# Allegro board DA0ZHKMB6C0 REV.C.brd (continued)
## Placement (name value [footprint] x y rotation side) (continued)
Q32  pj4n3kdw  [SC70-2_1-65-6P]  93.01 54.23 180 bottom
Q33  2n7002k  [SOT23_213-3_3-2]  138.5 47.32 270 bottom
Q34  2n7002k  [SOT23_213-3_3-2]  137 40.79 180 bottom
Q35  dtc144eua  [UMT_213-3-1_3]  132.81 40.67 0 bottom
Q36  2n7002k  [SOT23_213-3_3-2]  131.92 37.36 270 bottom
Q39  mmbt3904  [UMT_213-3-1_3]  25.37 9.17 180 bottom
Q40  pj4n3kdw  [SC70-2_1-65-6P]  48.23 74.7 180 top
Q41  2n7002k  [SOT23_213-3_3-2]  127.7 42.29 90 bottom
Q42  2n7002  [SOT23_213-3_3-2]  58.97 22.63 0 bottom
Q45  2n7002  [SOT23_213-3_3-2]  62.7 22.53 90 bottom
Q46  pj4n3kdw  [SC70-2_1-65-6P]  22.17 47.32 180 top
Q50  pj4n3kdw  [SC70-2_1-65-6P]  25.7 30.51 270 bottom
Q51  pj4n3kdw  [SC70-2_1-65-6P]  23.33 30.51 90 bottom
Q53  pj4n3kdw  [SC70-2_1-65-6P]  93.18 57.68 180 bottom
R7  *100/f_4  [RC0402]  64.66 87.35 0 top
R8  *100/f_4  [RC0402]  66.77 87.38 0 top
R9  *100/f_4  [RC0402]  69.05 87.38 0 top
R10  *100/f_4  [RC0402]  71.37 87.35 0 top
R11  2.2k_4  [RC0402]  62.2 87.11 0 top
R12  10_4  [RC0402]  85.56 85.62 90 top
R13  10_4  [RC0402]  86.58 85.62 90 top
R14  2.2k_4  [RC0402]  58 86.39 180 top
R15  *10k_4  [RC0402]  90.11 22.17 270 bottom
R17  *0/short_4  [SHORT0402]  88.74 84.35 270 top
R18  *0/short_4  [SHORT0402]  89.75 84.35 270 top
R19  10_4  [RC0402]  91.41 84.35 90 top
R20  10_4  [RC0402]  92.42 84.35 90 top
R21  *0/short_4  [SHORT0402]  22.09 83.77 180 bottom
R22  39.2k/f_4  [RC0402]  10.86 75.26 0 top
R23  *0/short_4  [SHORT0402]  13.63 64.39 135 top
R24  10k/f_4  [RC0402]  61.69 83.21 180 top
R25  *0/short_4  [SHORT0402]  15.05 66.07 180 top
R26  *0/short_4  [SHORT0402]  11.47 62.94 90 top
R27  56/f_4  [RC0402]  14.67 78.26 0 top
R28  *10k_4  [RC0402]  89.53 20.6 180 bottom
R29  *0/short_4  [SHORT0402]  159.56 81.56 180 top
R30  2.2k_4  [RC0402]  25.75 80.98 180 top
R31  200k/f_4  [RC0402]  44.14 75.13 270 top
R32  *0/short_4  [SHORT0402]  159.56 80.54 180 top
R33  0/j_8  [RC0805]  12.01 72.97 270 top
R34  *0/short_4  [SHORT0402]  78.6 82.88 0 top
R35  100k/j_4  [RC0402]  25.75 79.88 180 top
R36  *0/short_4  [SHORT0402]  91.61 76.2 90 top
R37  0/j_8  [RC0805]  28.52 80.47 180 top
R40  *0/short_4  [SHORT0402]  159.56 79.53 180 top
R41  10k_4  [RC0402]  87.32 76.78 0 top
R42  1m_4  [RC0402]  70.04 76.53 180 top
R44  *10k_4  [RC0402]  84.18 81.17 90 top
R45  20k/f_4  [RC0402]  27.14 78.87 180 top
R46  *0/short_4  [SHORT0402]  159.56 78.51 180 top
R47  *0/short_4  [SHORT0402]  16.22 78.26 90 top
R48  *10k_4  [RC0402]  72.64 79.25 270 top
R49  100k/f_4  [RC0402]  72.69 77.11 270 top
R50  *0/short_4  [SHORT0402]  159.56 77.5 180 top
R51  4.7k_4  [RC0402]  28.77 77.37 90 top
R52  47k_4  [RC0402]  31.31 78.31 270 top
R53  100k/f_4  [RC0402]  14.67 76.66 0 top
R54  10k_4  [RC0402]  85.32 81.17 270 top
R55  45.3/f_4  [RC0402]  75.75 77.12 90 top
R56  *0/short_4  [SHORT0402]  73.7 77.9 90 top
R57  *0_4  [RC0402]  74.72 77.11 90 top
R58  100k/f_4  [RC0402]  85.16 75.54 180 top
R59  10m_4  [RC0402]  79.54 76.66 0 top
R60  *10k_4  [RC0402]  85.16 68.55 180 top
R61  *10k_4  [RC0402]  87.54 67.39 0 top
R62  4.7k_4  [RC0402]  45.69 76.56 0 top
R63  200/f_4  [RC0402]  89.45 76.78 0 top
R64  *10k_4  [RC0402]  85.23 76.78 0 top
R65  33_4  [RC0402]  27.37 75.34 0 top
R66  56/f_4  [RC0402]  14.67 81.36 0 top
R67  4.7k_4  [RC0402]  45.43 74.45 270 top
R68  2.2k_4  [RC0402]  16.35 74.57 180 top
R70  *100k/f_4  [RC0402]  36.36 70.6 90 top
R71  *100k/f_4  [RC0402]  37.63 70.6 90 top
R73  2.2k_4  [RC0402]  51.78 70.64 180 top
R74  10k_4  [RC0402]  53.97 70.84 180 top
R79  2.2k_4  [RC0402]  51.78 69.14 180 top
R80  2.2k_4  [RC0402]  53.94 69.14 180 top
R81  *10k_4  [RC0402]  85.46 67.54 180 top
R82  *1k_4  [RC0402]  26.76 70.13 0 top
R83  *0/short_4  [SHORT0402]  51.78 68.1 0 top
R84  4.7k_4  [RC0402]  53.94 68.1 180 top
R85  ntpm@10k_4  [RC0402]  86.02 67.67 0 bottom
R86  *0_4  [RC0402]  90.77 67.69 180 bottom
R87  *0_4  [RC0402]  95.83 70.59 270 bottom
R88  *10k_4  [RC0402]  85.44 65.84 270 top
R90  22_4  [RC0402]  53.94 67.08 180 top
R91  1/f_4  [RC0402]  137.25 67.08 270 top
R92  1/f_4  [RC0402]  138.27 67.08 270 top
R93  1/f_4  [RC0402]  139.41 67.08 270 top
R94  1/f_4  [RC0402]  140.55 67.08 270 top
R95  1/f_4  [RC0402]  141.7 67.08 270 top
R96  1/f_4  [RC0402]  142.84 67.08 270 top
R97  2.49k/f_4  [RC0402]  143.98 67.46 90 top
R98  22_4  [RC0402]  51.78 66.85 180 top
R99  1/f_4  [RC0402]  135.09 66.83 270 top
R100  1/f_4  [RC0402]  136.24 66.83 270 top
R101  10k_4  [RC0402]  30.8 70.74 0 top
R102  33_4  [RC0402]  51.81 65.84 0 top
R103  33_4  [RC0402]  53.94 65.71 0 top
R104  10k_4  [RC0402]  86.96 65.89 0 top
R105  10k_4  [RC0402]  89.65 65.25 0 top
R106  *0/short_6  [SHORT0603]  25.49 64.67 270 top
R107  *0/short_6  [SHORT0603]  26.76 64.67 270 top
R108  22_4  [RC0402]  51.76 63.58 0 top
R109  33_4  [RC0402]  51.76 64.62 0 top
R110  33_4  [RC0402]  53.94 64.67 0 top
R111  *100k/j_4  [RC0402]  24.35 64.67 90 top
R112  *10k_4  [RC0402]  103.22 64.67 270 top
R113  10k_4  [RC0402]  104.23 65.35 270 top
R114  100k/f_4  [RC0402]  105.25 64.67 270 top
R115  10k_4  [RC0402]  107.53 64.16 180 top
R116  *0/short_4  [SHORT0402]  85.31 64.03 180 top
R117  22_4  [RC0402]  53.94 63.63 0 top
R118  560_4  [RC0402]  49.62 64.67 180 top
R119  560_4  [RC0402]  49.67 63.65 180 top
R120  *0/short_4  [SHORT0402]  90.03 62.97 180 top
R121  *0/short_4  [SHORT0402]  85.31 63.02 180 top
R122  *0/short_4  [SHORT0402]  32.71 62.99 0 top
R124  10k_4  [RC0402]  31.31 76.28 270 top
R127  73.2/f_4  [RC0402]  89.85 60.68 0 top
R128  71.5/f_4  [RC0402]  89.63 61.87 180 top
R129  20/f_4  [RC0402]  85.31 61.75 180 top
R130  *0/short_4  [SHORT0402]  91.79 61.75 180 top
R131  *0/short_4  [SHORT0402]  97.37 61.24 0 top
R133  10k_4  [RC0402]  107.74 61.27 180 top
R134  *0/short_4  [SHORT0402]  85.18 60.73 0 top
R135  16.9r_4  [RC0402]  87.6 60.73 180 top
R139  *0/short_4  [SHORT0402]  97.37 60.1 0 top
R140  *2.2k_4  [RC0402]  53.48 60.2 270 top
R144  10k_4  [RC0402]  107.88 59.42 180 top
R145  *2.2k_4  [RC0402]  52.92 58.6 0 top
R146  10k_4  [RC0402]  87.6 58.57 180 top
R147  *10k_4  [RC0402]  89.88 58.57 0 top
R148  *0/short_6  [SHORT0603]  45.63 58.01 90 top
R149  *0/short_6  [SHORT0603]  44.01 58.01 90 top
R150  10k_4  [RC0402]  145.63 57.94 270 top
R153  *4.7k_4  [RC0402]  47.84 57.3 0 top
R154  620/f_4  [RC0402]  97.68 56.03 0 top
R155  *2.2k_4  [RC0402]  52.9 57.48 0 top
R156  *2.2k_4  [RC0402]  52.85 56.21 0 top
R159  *0/short_4  [SHORT0402]  99.28 55.02 180 top
R160  10k/j_4  [RC0402]  118.58 54.76 0 top
R161  *0_4  [RC0402]  99.28 54 0 top
R162  10k/j_4  [RC0402]  23.46 38.61 0 bottom
R163  402/f_4  [RC0402]  63.97 65.94 180 bottom
R164  10k/j_4  [RC0402]  118.58 52.48 0 top
R165  2.2_6  [RC0603]  129.89 51.46 180 top
R166  0/j_6  [RC0603]  124.55 51.08 90 top
R167  8.2k_4  [RC0402]  55.29 64.16 0 bottom
R171  100k/f_4  [RC0402]  132.3 48.54 270 top
R172  *0_4  [RC0402]  40.35 48.29 180 top
R173  *0/short_4  [SHORT0402]  140.05 48.03 180 top
R178  tpm@2.2_6  [RC0603]  49.97 37.8 180 top
R180  *20k_4  [RC0402]  43.12 37.59 270 top
R181  tpm_i@4.7k_4  [RC0402]  45.15 37.59 90 top
R182  *4.7k_4  [RC0402]  44.14 37.59 90 top
R184  100k_4  [RC0402]  22.77 44.86 270 top
R185  100k_4  [RC0402]  23.79 44.86 270 top
R186  10k_4  [RC0402]  19.89 56.01 0 top
R187  1m_4  [RC0402]  26.74 33.12 0 bottom
R188  *0/short_6  [SHORT0603]  10 9.8 270 top
R189  *0/short_6  [SHORT0603]  11.65 9.8 270 top
R190  *0/short_6  [SHORT0603]  13.3 9.8 270 top
R191  *0/short_6  [SHORT0603]  14.82 9.55 270 top
R192  100/f_4  [RC0402]  54.58 84.68 0 bottom
R193  100/f_4  [RC0402]  77.79 95.45 180 bottom
R194  560_4  [RC0402]  77.79 98.5 180 bottom
R195  560_4  [RC0402]  56.61 83.54 180 bottom
R196  10k_4  [RC0402]  163.25 99.09 0 bottom
R197  *0/short_4  [SHORT0402]  54.58 82.27 180 bottom
R198  *0_4  [RC0402]  56.61 82.27 180 bottom
R200  0/j_4  [RC0402]  165.91 97.69 180 bottom
R201  *0/j_4  [RC0402]  162.1 96.93 180 bottom
R202  *0/j_4  [RC0402]  165.91 96.67 180 bottom
R203  4.7k_4  [RC0402]  163.63 96.42 270 bottom
R204  *0/j_4  [RC0402]  162.1 95.78 180 bottom
R205  *0/j_4  [RC0402]  165.91 95.66 180 bottom
R206  10k_4  [RC0402]  62.58 89.69 270 bottom
R207  *0/short_8  [SHORT0805]  165.79 89.56 270 bottom
R208  620/f_4  [RC0402]  64.1 89.43 270 bottom
R209  620/f_4  [RC0402]  65.12 89.43 270 bottom
R210  620/f_4  [RC0402]  66.26 89.43 270 bottom
R211  620/f_4  [RC0402]  67.28 89.43 270 bottom
R212  620/f_4  [RC0402]  68.55 89.43 270 bottom
R213  620/f_4  [RC0402]  69.56 89.43 270 bottom
R214  620/f_4  [RC0402]  70.83 89.43 270 bottom
R215  620/f_4  [RC0402]  71.85 89.43 270 bottom
R216  *0/j_4  [RC0402]  162.61 87.78 0 bottom
R217  0/j_4  [RC0402]  162.61 86.77 0 bottom
R218  2.2k_4  [RC0402]  62.32 87.27 90 bottom
R219  2.2k_4  [RC0402]  63.34 87.27 90 bottom
R220  100k/f_4  [RC0402]  59.27 86.26 180 bottom
R221  *100k/f_4  [RC0402]  62.09 83.08 90 bottom
R222  *4.7k_4  [RC0402]  159.18 82.19 90 bottom
R223  *4.7k_4  [RC0402]  160.33 82.19 90 bottom
R224  *1m_8  [RC0805]  144.47 83.69 270 bottom
R225  75/f_8  [RC0805]  130.39 82.6 90 bottom
R226  75/f_8  [RC0805]  133.75 82.6 90 bottom
R227  75/f_8  [RC0805]  137.43 82.6 90 bottom
R228  75/f_8  [RC0805]  140.61 82.07 90 bottom
R230  *10k_4  [RC0402]  83.61 79.02 0 bottom
R231  10k/f_4  [RC0402]  163.37 77.88 270 bottom
R232  4.7k_4  [RC0402]  163.37 75.72 270 bottom
R233  *0_4  [RC0402]  22.42 37.39 270 top
R234  1m_4  [RC0402]  22.8 27.28 90 bottom
R235  10k_4  [RC0402]  95.98 74.65 270 bottom
R236  100/f_4  [RC0402]  59.02 74.57 180 bottom
R237  10k_4  [RC0402]  56.73 74.45 180 bottom
R238  *0/short_4  [SHORT0402]  78.32 73.05 0 bottom
R239  10k_4  [RC0402]  57.5 72.77 90 bottom
R240  *0/short_4  [SHORT0402]  76.24 72.32 90 bottom
R241  10k_4  [RC0402]  96.49 72.29 0 bottom
R242  10k_4  [RC0402]  58.56 72.97 90 bottom
R243  10k_4  [RC0402]  55.06 71.88 270 bottom
R244  *0/short_4  [SHORT0402]  83.2 70.89 0 bottom
R245  *10k_4  [RC0402]  96.79 68.3 90 top
R246  10k_4  [RC0402]  56.48 72.72 90 bottom
R247  45.3/f_4  [RC0402]  80.48 70.38 90 bottom
R248  1k/f_4  [RC0402]  78.14 70.28 270 bottom
R249  1k/f_4  [RC0402]  79.16 70.28 270 bottom
R250  51/f_4  [RC0402]  77.13 70.26 90 bottom
R251  51/f_4  [RC0402]  83.6 69.78 180 bottom
R252  *0/short_4  [SHORT0402]  56.73 69.62 180 bottom
R253  *10k_4  [RC0402]  53.86 69.77 90 bottom
R254  *10k_4  [RC0402]  54.88 69.77 270 bottom
R255  4.02k/f_4  [RC0402]  71.47 69.3 180 bottom
R256  *10k_4  [RC0402]  50.38 73.56 0 bottom
R257  *0/short_4  [SHORT0402]  74.76 68.89 270 bottom
R258  1.24k/f_4  [RC0402]  75.78 68.89 90 bottom
R259  51/f_4  [RC0402]  83.6 68.76 180 bottom
R260  *10k_4  [RC0402]  56.86 70.89 0 bottom
R261  47.5/f_4  [RC0402]  71.47 68.29 180 bottom
R262  51/f_4  [RC0402]  81.42 68.2 270 bottom
R263  402/f_4  [RC0402]  65.68 69.55 0 bottom
R264  402/f_4  [RC0402]  67.53 67.97 270 bottom
R265  *10k_4  [RC0402]  54.32 67.84 180 bottom
R266  10k_4  [RC0402]  94 67.32 180 bottom
R267  51/f_4  [RC0402]  83.53 67.72 180 bottom
R268  *10k_4  [RC0402]  95.65 68.33 90 top
R269  *10k_4  [RC0402]  53.94 66.7 180 bottom
R270  *0_4  [RC0402]  76.67 66.4 0 bottom
R271  tpm@10k_4  [RC0402]  83.53 66.7 0 bottom
R272  *0/short_4  [SHORT0402]  71.16 66.24 0 bottom
R273  *0_4  [RC0402]  60.67 66.19 180 bottom
R274  22_4  [RC0402]  54.32 65.68 180 bottom
R275  *0/short_4  [SHORT0402]  32.38 64.31 180 bottom
R276  100k/f_4  [RC0402]  34.41 64.31 0 bottom
R277  *0/short_4  [SHORT0402]  36.44 64.31 180 bottom
R278  *0/short_8  [SHORT0805]  148.05 64.8 270 bottom
R279  22_4  [RC0402]  55.29 63.09 180 bottom
R280  10k_4  [RC0402]  88.1 64.31 270 bottom
R281  *0/short_4  [SHORT0402]  101.31 59.51 180 bottom
R282  *0/short_4  [SHORT0402]  85.26 64.37 0 bottom
R283  *0/short_4  [SHORT0402]  98.39 64.29 0 bottom
R284  49.9/f_4  [RC0402]  57.65 63.55 0 bottom
R285  49.9/f_4  [RC0402]  58.64 66.19 180 bottom
R286  49.9/f_4  [RC0402]  62.07 68.43 90 bottom
R287  *0/short_4  [SHORT0402]  86.96 63.4 270 bottom
R288  *0/short_4  [SHORT0402]  85.26 63.35 0 bottom
R289  2.2k_4  [RC0402]  98.39 63.27 180 bottom
R290  *0/short_4  [SHORT0402]  87.98 62.18 90 bottom
R291  10k_4  [RC0402]  85 62.28 0 bottom
R292  *0_4  [RC0402]  54.19 62.08 180 bottom
R293  49.9/f_4  [RC0402]  58.18 61.6 0 bottom
R294  *0/short_4  [SHORT0402]  31.74 61.14 180 bottom
R295  10k_4  [RC0402]  85.05 61.2 0 bottom
R296  100/f_4  [RC0402]  74.39 60.86 180 bottom
R297  *100k_4  [RC0402]  35.02 74.19 90 top
R298  *10k_4  [RC0402]  148.71 60.68 180 bottom
R299  49.9/f_4  [RC0402]  75.66 62.13 180 bottom
R300  200k/f_4  [RC0402]  90.01 60.33 0 bottom
R301  10k_4  [RC0402]  85.06 60.19 0 bottom
R302  0.2a/600ohm_6  [RC0603]  54.58 60.25 90 bottom
R303  2.2k_4  [RC0402]  77.44 57.68 180 bottom
R304  10k_4  [RC0402]  90.01 59.31 180 bottom
R305  3.3k/f_4  [RC0402]  87.64 62.41 270 top
R306  100k/j_4  [RC0402]  105.38 59.08 270 bottom
R307  10k/f_4  [RC0402]  34.26 58.9 270 bottom
R308  *47k_4  [RC0402]  103.85 58.83 180 bottom
R309  *0/short_4  [SHORT0402]  48 58.17 0 bottom
R310  0/j_4  [RC0402]  131.79 58.57 270 bottom
R311  0/j_4  [RC0402]  133.06 58.57 270 bottom
R312  *10k_4  [RC0402]  60.87 58.47 90 bottom
R313  *0/short_6  [SHORT0603]  142.84 58.45 270 bottom
R314  100/f_4  [RC0402]  75.91 60.48 270 bottom
R315  *0/short_4  [SHORT0402]  90.11 58.24 0 bottom
R316  0_4  [RC0402]  12.11 56.9 270 top
R317  10k_4  [RC0402]  54.32 58.06 180 bottom
R318  3.3k/f_4  [RC0402]  134.97 58.95 0 bottom
R319  3.3k/f_4  [RC0402]  137 58.06 180 bottom
R320  *10k_4  [RC0402]  92.4 67.87 90 bottom
R321  *0/short_4  [SHORT0402]  80.86 57.18 90 bottom
R322  *0/j_4  [RC0402]  105.38 57.05 270 bottom
R323  10k_4  [RC0402]  90.52 56.67 90 bottom
R324  *10k_4  [RC0402]  96.84 70.59 90 bottom
R325  *0/short_4  [SHORT0402]  47.95 55.78 0 bottom
R326  *0/short_4  [SHORT0402]  89.53 19.51 180 bottom
R327  *10k_6_ntc  [RC0603]  137.9 55.78 90 bottom
R328  10k_4  [RC0402]  90.01 55.02 0 bottom
R329  *15k_4  [RC0402]  150.46 54.76 90 bottom
R330  1k_4  [RC0402]  152.11 54.76 270 bottom
R331  *0/short_4  [SHORT0402]  47.95 54.74 0 bottom
R332  *0/short_6  [SHORT0603]  59.73 54.31 0 bottom
R333  *0/short_4  [SHORT0402]  57.88 53.87 270 bottom
R334  *0/short_4  [SHORT0402]  62.27 53.77 180 bottom
R335  *0/short_4  [SHORT0402]  47.95 53.62 0 bottom
R336  100k/f_4  [RC0402]  67.6 53.14 180 bottom
R337  *0_4  [RC0402]  137.38 52.73 90 bottom
R338  4.7k_4  [RC0402]  95.67 52.68 90 bottom
R339  100k/f_4  [RC0402]  67.6 52.12 180 bottom
R340  *0/short_8  [SHORT0805]  56.48 51.84 180 bottom
R341  *0/short_8  [SHORT0805]  56.48 49.66 180 bottom
R342  4.7k_4  [RC0402]  67.09 49.43 0 bottom
R343  100k/f_4  [RC0402]  145.76 48.41 180 bottom
R344  4.7k_4  [RC0402]  67.09 48.21 180 bottom
R345  *10k/j_4  [RC0402]  137.63 50.83 0 bottom
R346  *0/short_6  [SHORT0603]  56.23 47.88 180 bottom
R347  29.4/f_4  [RC0402]  68.74 47.68 270 bottom
R348  162/f_4  [RC0402]  69.76 47.68 90 bottom
R349  23.2/f_4  [RC0402]  70.78 47.68 270 bottom
R350  *0/short_4  [SHORT0402]  112.3 14.98 270 bottom
R351  *1.24k/f_4  [RC0402]  74.41 71.07 180 bottom
R352  *0/short_4  [SHORT0402]  132.17 46.25 270 bottom
R353  0/j_4  [RC0402]  134.2 46.25 90 bottom
R354  0/j_4  [RC0402]  135.35 46.25 90 bottom
R355  1m_4  [RC0402]  14.09 37.64 90 bottom
R356  1m_4  [RC0402]  16.15 38.35 0 bottom
R357  0/j_6  [RC0603]  141.57 44.81 0 bottom
R358  100k/j_4  [RC0402]  134.97 43.71 270 bottom
R359  *100k_4  [RC0402]  131.92 44.22 270 bottom
R360  *0/short_6  [SHORT0603]  142.51 88.01 180 bottom
R361  2.2_6  [RC0603]  137.76 43.97 90 bottom
R362  100k/j_4  [RC0402]  145.76 43.97 180 bottom
R363  0_4  [RC0402]  21.54 54.92 0 top
R364  4.7k_4  [RC0402]  95.62 55.58 270 bottom
R365  *0_4  [RC0402]  22.37 53.37 90 top
R366  *47k/f_4  [RC0402]  145.76 42.82 180 bottom
R367  10k_4  [RC0402]  102.2 64.16 270 top
R368  100k/f_4  [RC0402]  145.76 41.81 180 bottom
R370  10k_4  [RC0402]  123.79 41.3 0 bottom
R371  10k_4  [RC0402]  130.57 40.95 270 bottom
R372  *0/short_4  [SHORT0402]  123.79 40.28 0 bottom
R373  *0/short_4  [SHORT0402]  145.76 39.78 0 bottom
R374  *43_4  [RC0402]  123.79 39.27 180 bottom
R375  *0/short_4  [SHORT0402]  145.76 38.76 0 bottom
R376  2.2_6  [RC0603]  141.44 38.51 180 bottom
R377  *100k_4  [RC0402]  134.33 38.25 270 bottom
R378  4.7k_4  [RC0402]  141.61 37.13 0 bottom
R382  10k/j_4  [RC0402]  123.77 38.25 0 bottom
R383  10k/j_4  [RC0402]  146.07 38.61 0 top
R384  4.7k_4  [RC0402]  141.92 36.11 0 bottom
R385  *10k_4  [RC0402]  134.33 36.09 90 bottom
R386  10k/j_4  [RC0402]  147.14 37.07 90 top
R387  *100k/f_4  [RC0402]  123.92 35.13 0 bottom
R388  4.7k/f_4  [RC0402]  103.47 35.08 180 bottom
R389  10k/f_4  [RC0402]  47.02 34.82 180 bottom
R390  *0/short_6  [SHORT0603]  105.19 34.82 270 bottom
R391  4.7k_4  [RC0402]  123.79 34.11 0 bottom
R392  4.7k/f_4  [RC0402]  103.47 34.06 0 bottom
R393  10k/f_4  [RC0402]  47.02 33.8 180 bottom
R394  *10k_4  [RC0402]  147.71 34.83 180 bottom
R395  10k_4  [RC0402]  123.79 33.1 0 bottom
R396  *0_6  [RC0603]  105.63 32.41 0 bottom
R397  4.7k/f_4  [RC0402]  65.12 29.87 0 bottom
R398  *10k/f_4  [RC0402]  46.51 29.61 180 bottom
R399  4.7k/f_4  [RC0402]  63.59 25.81 0 bottom
R401  *0_6  [RC0603]  65.19 22.76 90 bottom
R402  *0/short_8  [SHORT0805]  161.38 23.65 270 bottom
R404  2.2k_4  [RC0402]  49.75 17.63 180 bottom
R405  10k_4  [RC0402]  52.54 19.81 90 bottom
R406  10k_4  [RC0402]  53.56 19.84 90 bottom
R407  *0/short_8  [SHORT0805]  57.09 17.09 0 bottom
R408  2.2k_4  [RC0402]  47.59 17.63 0 bottom
R411  *0_8  [RC0805]  57.09 19.1 0 bottom
R412  1k_4  [RC0402]  29.05 9.04 90 bottom
R413  20k_4  [RC0402]  37.05 10.44 270 bottom
R414  150k/f_4  [RC0402]  22.7 9.42 270 bottom
R415  20k_4  [RC0402]  37.05 8.15 90 bottom
R416  68.1k/f_4  [RC0402]  22.7 7.26 270 bottom
R417  4.7k_4  [RC0402]  25.11 7.14 180 bottom
R418  4.7k_4  [RC0402]  27.91 9.04 270 bottom
R419  *10k_4  [RC0402]  41.62 53.06 180 top
R420  *0/j_4  [RC0402]  126.71 38.76 90 bottom
R426  200k/f_4  [RC0402]  47.21 18.64 180 bottom
R427  *0/short_8  [SHORT0805]  162.4 41.94 270 bottom
R428  *10k_4  [RC0402]  12.01 67.26 180 top
R510  1k_4  [RC0402]  12.01 70.69 0 top
R511  1k_4  [RC0402]  12.01 68.4 0 top
R513  10k_4  [RC0402]  52.42 21.92 90 bottom
R514  4.7k_4  [RC0402]  16.98 83.34 180 top
R515  4.7k_4  [RC0402]  16.98 82.19 180 top
R516  *0/short_4  [SHORT0402]  153.76 70 180 bottom
R521  *10k_4  [RC0402]  36.26 63.88 90 top
R522  10k_4  [RC0402]  139.64 39.7 270 bottom
R523  10k_4  [RC0402]  59.81 20.32 0 bottom
R526  tpm_i@0_4  [RC0402]  41.58 37.19 180 top
R527  *0_4  [RC0402]  38.37 36.68 180 top
R528  tpm_n@0_4  [RC0402]  38.37 38.35 180 top
R530  tpm_i@0_4  [RC0402]  49.37 40.72 90 top
R533  tpm_n@0_4  [RC0402]  48.38 44.04 270 top
R534  10k_4  [RC0402]  59.81 19.28 0 bottom
R535  *0/short_4  [SHORT0402]  127.22 37.08 180 bottom
R536  *10k/j_4  [RC0402]  40.05 15.7 0 bottom
R537  *0/j_4  [RC0402]  163.29 80.01 90 bottom
R539  tpm@10k_4  [RC0402]  43.18 50.28 270 top
R540  0_4  [RC0402]  20.88 31.57 0 top
R541  0_4  [RC0402]  21.34 51.91 90 top
R542  0_4  [RC0402]  22.41 49.54 90 top
R543  0_4  [RC0402]  21.76 44.4 90 top
R544  0_4  [RC0402]  21.66 34.83 0 top
R545  *100k_4  [RC0402]  22.77 32.24 90 top
R546  *100k_4  [RC0402]  20.31 52.31 90 top
R547  *100k_4  [RC0402]  20.36 49.56 90 top
R548  *100k_4  [RC0402]  22.76 35.87 0 top
R549  *100k_4  [RC0402]  22.73 33.78 0 top
R550  0_4  [RC0402]  94.43 70.84 180 top
R551  *0_4  [RC0402]  94.07 69.29 90 top
R552  *0_6  [RC0603]  5.68 85.29 270 bottom
RP6  10k_10p8r  [10P8R]  137.38 37.11 90 bottom
SW6  misaki_sw_h1.5  [SW-NTC031-AB1G-A160T-4P]  32.9 86.28 0 top
SW8  misaki_sw_h1.5  [SW-NTC031-AB1G-A160T-4P]  100.6 4.5 270 bottom
T2  *rclamp0531t  [RC0402]  72.08 82.78 180 top
T3  *rclamp0531t  [RC0402]  72.3 84.48 270 top
T10  *0.2pf/5v_4  [RC0402]  19.17 54.47 90 top
T11  *0.2pf/5v_4  [RC0402]  21.09 30 90 top
T12  *0.2pf/5v_4  [RC0402]  21.19 33.23 90 top
T13  *0.2pf/5v_4  [RC0402]  21.15 36.37 270 top
T14  *0.2pf/5v_4  [RC0402]  21.38 49.55 270 top
T15  *0.2pf/5v_4  [RC0402]  20.72 53.85 0 top
TP6  *pad  [TP2050]  57.37 83.34 180 top
TP8  *pad  [TP2050]  62.65 78.51 270 top
TP9  *pad  [TP2050]  63.8 79.45 270 top
TP15  *pad  [TP2050]  101.18 63.58 0 top
TP16  *pad  [TP2050]  84.7 58.93 90 top
TP17  *pad  [TP2050]  86.2 58.57 90 top
TP18  *  [TP2650]  139.92 50.57 180 top
TP19  *  [TP2650]  130.93 47.98 180 top
TP20  *  [TP2650]  143.98 30.12 0 top
TP21  *pad  [TP2050]  54.6 54.86 0 top
TP22  *pad  [TP2050]  59.45 73.51 180 bottom
TP23  *pad  [TP2050]  125.83 70.92 0 bottom
TP24  *pad  [TP2050]  79.09 64.67 180 bottom
TP25  *pad  [TP2050]  72.68 64.06 270 bottom
TP26  *pad  [TP2050]  67.33 58.7 270 bottom
TP27  *  [TP2650]  54.47 57.48 0 top
TP31  *  [TP2650]  125.62 39.5 0 bottom
TP32  *  [TP2650]  54.46 56.21 0 top
TP33  *  [TP2650]  54.47 60.12 180 top
TP34  *  [TP2650]  54.45 58.78 0 top
TP35  *pad  [TP2050]  53.33 55.14 180 top
TP36  *  [TP2650]  122.24 39.32 0 bottom
TP38  *  [TP2650]  126.76 36.09 0 bottom
TP40  *  [TP2650]  133.47 43.87 0 bottom
TP41  *  [TP2650]  129.53 37.06 0 bottom
TP43  *  [TP2650]  125.42 36.88 0 bottom
TP44  *  [TP2650]  128.26 38.18 0 bottom
TP45  *  [TP2650]  139.41 41.55 0 bottom
TP48  *  [TP2650]  77.72 60.2 180 bottom
TP49  *  [TP2650]  85.69 59.74 0 top
TP50  *  [TP2650]  80.88 59.56 180 bottom
TP51  *  [TP2650]  86.83 60.48 180 bottom
TP52  *  [TP2650]  65.98 72.64 180 bottom
TP53  *  [TP2650]  67.22 73.01 180 bottom
TP54  *pad  [TP2050]  102.02 63.73 180 bottom
TP55  *pad  [TP2050]  106.18 59.58 0 top
TP56  *pad  [TP2050]  103.55 55.22 180 bottom
TP57  *pad  [TP2050]  102.43 56.46 180 bottom
TP58  *pad  [TP2050]  106.49 56.85 0 top
TP59  *pad  [TP2050]  106.49 58.12 0 top
TP99  *pad  [TP2675]  38.78 48.16 90 top
TP100  *pad  [TP2675]  36.41 41.76 90 top
TP101  *pad  [TP2675]  37.3 40.03 90 top
U3  dmic-kmm47237626-06dt  [MIC-FM-M201-U03-6P]  77.1 86.21 180 top
U7  emc1412-1-aczl-tr  [MSOP8-4_9-65]  59.78 80.67 90 top
U8  ns692417  [TRF-9_4-1_27-24P]  135.98 79.02 0 top
U9  alc283  [QFN48-6X6-4-49P-ALC280]  22.06 74.57 90 top
U11  rtl8111gs-cg  [QFN32-4X4-4-33P-0_9H]  146.02 62.51 270 top
U12  vlv_m_d/bga  [BGA1170-INTEL-BAY-TRAIL]  69.56 60.5 180 top
U13  gl850g-ohy31  [QFN28-5X5-5-29P-GL850G]  102.62 59.44 0 top
U16  tpm@npct620/650_tssop28  [TSSOP28-6_4-65-SLB9635TT]  42.76 43.08 0 top
U18  npce985la0dx  [LQFP128-16X16-4]  134.46 38.25 270 top
U19  g524b2t11u  [SOT23-5-2_8-95-5P-1_3H]  82.01 86.64 0 bottom
U21  g5243at11u  [SOT23-2_8-95-6P]  26.64 60.48 0 bottom
U22  spi_flash  [SOIC8-7_9-1_27]  133.7 52.4 180 bottom
U24  *g2129tl1u  [SC70-2_1-65-6P]  40.35 50.83 180 top
U25  74lvc2g07gw  [SC70-2_1-65-6P-0_95H]  92.68 65.68 0 bottom
U26  74lvc2g07gw  [SC70-2_1-65-6P-0_95H]  52.11 71.93 180 bottom
U27  pca9306  [VSSOP8-3_1-5-8P]  49.62 20.8 0 bottom
U30  em@h26m64003dqr  [BGA169-SANDISK-SDIN5C-32G]  101.74 19.1 270 bottom
VC6  *tvm0g5r5m220r  [CC0402]  58.26 89.18 0 bottom
Y6  25mhz +-10ppm  [XTL-3_2X2_5-2_2X1_7]  69.56 79.78 180 top
Y7  32.768khz  [XTL-3_2X1_5-2_5-0_8H]  78.83 80.04 180 top
Y8  25mhz +-30ppm  [XTL-3_2X2_5-2_2X1_7]  146.37 70.1 0 top
Y9  12mhz  [XTL-3_2X2_5-2_2X1_8-4P]  103.34 51.69 0 top

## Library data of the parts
C4 C5 C7-C19 C22-C27 C30-C49 C51-C53 C55-C57 C59-C61 C63-C72 C75-C80 C82-C87 C89-C92 C94-C98 C102 C105-C110 C118 C119 C123-C133 C136-C142 C144 C145 C147-C149 C151-C157 C159-C162 C164 C165 C170-C174 C181-C183 C185-C191 C193-C197 C199 C200 C202-C205 C207-C211 C214-C224 C226-C229 C234 C238-C241 C243-C254 C256-C268 C270 C272-C276 C278 C279 C288 C294-C296 C302 C304 C307-C311 C314-C323 C329-C333 C335-C339 C341-C343 C347 C351 C356 C358 C359 D7 D8 D15 PC9 PC10 PC16-PC18 PC20 PC23-PC30 PC32-PC34 PC36 PC38-PC43 PC46-PC49 PC56 PC57 PC59-PC63 PC67-PC73 PC75 PC77 PC78 PC82 PC84 PC86-PC91 PC93 PC97-PC100 PC102-PC105 PC108-PC110 PC112 PC113 PC115 PC116 PC118-PC121 PC123-PC126 PC128 PC129 PC131-PC143 PC145-PC147 PC152 PC154 PC155 PC157-PC160 PC163-PC165 PC167-PC169 PC171-PC174 PC176 PC178 PC181 PC182 PC184 PC186 PC189-PC191 PC193-PC198 PC200-PC202 PC204 VC6 = CC0402
C20 C21 = CC1206
C28 = CC1808
C50 C58 C62 C101 C103 C104 C134 C143 C146 C158 C167 C175 C176 C178-C180 C184 C198 C206 C225 C230-C233 C235-C237 C242 C255 C271 C277 C282 C284 C290 C292 C293 C298-C301 C303 C305 C324-C328 C340 C344 C345 C348-C350 C355 C357 PC12 PC15 PC19 PC21 PC22 PC31 PC35 PC37 PC44 PC45 PC50 PC52-PC55 PC58 PC64-PC66 PC83 PC85 PC95 PC101 PC111 PC114 PC117 PC122 PC127 PC130 PC148 PC149 PC151 PC156 PC161 PC162 PC166 PC170 PC183 PC185 PC187 PC188 PC192 PC199 PC203 PC205 = CC0603
C73 C74 C192 PC8 PC13 PC76 PC79 PC81 PC94 PC96 PC106 PC107 PC150 PC153 PC175 PC177 PC179 PC180 = CC0805
C115 PC7 PC14 = CC7343
C135 = CC3528
CN4 = SDCARD-CS1S-441-H-N-11P
CN6 = USB-53063-00902-001-9P-SMT
CN7 = HDMI-HDM-19DVXB-19P
CN8 = USB-020133GR004M22BZL-4P
CN9 = RJ45-C100MP-10809-L-8P
CN10 = MINIPCI-80053-1023-52P-SMT
CN11 = PHJK-2SJ3072-108111F-6P
CN14 = SATA-C166KN-12209-L-22P-L-SMT
CN15 = ML1220-SMT
CN16 = MSC-RB30-5-FG-30P-L-SMT
CN17 = 85208-24071-24P-L
CN18 = 88513-0801-8P-L
CN19 = 88266-040XX-XXX-4P-L
CP6-CP11 = 8P4R
D6 D11 D14 D17 D18 D20 D37 L1 PR6-PR10 PR13-PR21 PR27 PR29 PR32 PR36 PR37 PR39 PR41 PR43 PR45 PR46 PR48 PR52 PR53 PR59-PR61 PR63-PR65 PR75 PR76 PR79-PR84 PR87-PR90 PR95 PR96 PR98 PR99 PR102 PR104 PR106 PR108 PR111 PR112 PR115-PR122 PR124 PR129 PR130 PR136-PR140 PR142 PR143 PR148 PR150 PR151 PR153 PR158 PR170-PR174 PR178-PR180 PR184 R7-R15 R19 R20 R22 R24 R27 R28 R30 R31 R35 R41 R42 R44 R45 R48 R49 R51-R55 R57-R68 R70 R71 R73 R74 R79-R82 R84-R88 R90-R105 R108-R115 R117-R119 R124 R127-R129 R133 R135 R140 R144-R147 R150 R153-R156 R160-R164 R167 R171 R172 R180-R182 R184-R187 R192-R196 R198 R200-R206 R208-R223 R230-R237 R239 R241-R243 R245-R251 R253-R256 R258-R271 R273 R274 R276 R279 R280 R284-R286 R289 R291-R293 R295-R301 R303-R308 R310-R312 R314 R316-R320 R322-R324 R328-R330 R336-R339 R342-R345 R347-R349 R351 R353-R356 R358 R359 R362-R368 R370 R371 R374 R377 R378 R382-R389 R391-R395 R397-R399 R404-R406 R408 R412-R420 R426 R428 R510 R511 R513-R515 R521-R523 R526-R528 R530 R533 R534 R536 R537 R539-R551 T2 T3 T10-T15 = RC0402
D9 D10 D16 D19 D24 D31 D32 D35 PD7-PD12 = DSM
D33 D34 L10 L14 L18 PR12 PR24 PR25 PR33 PR34 PR40 PR47 PR51 PR56 PR69 PR74 PR77 PR85 PR91 PR92 PR103 PR109 PR113 PR134 PR146 PR157 PR166-PR168 PR182 PR185 R165 R166 R178 R302 R327 R357 R361 R376 R396 R401 R552 = RC0603
D36 = SOT323_213-2_1-1_3-2N7002W
G6 G7 = SOLDERJUMPER-2
HOLE7 = O-ZHJ-9
HOLE8 = HG-TC276BC335D118P2
HOLE9 = O-ZHJ-21
HOLE10 HOLE11 HOLE13 = H-C197D140P2
HOLE12 = HG-TC394BC236D118P2
HOLE14 = HG-C492D335P2
HOLE15 HOLE16 = HG-TC256BC354D118P2
HOLE17 HOLE18 = H-TC197BC83D83PT
HOLE19 = HG-TC315BC276D118P2
HOLE20 = H-O39X475D39X475N
HOLE21 = H-O39X279D39X279N
HOLE22 = H-C236D118P2
HOLE23 = H-C51D51N
HOLE24 = H-C70D70N
JDIM6 = DDR-DDRSK-20401-TP4B-204P-SMT
L7 = CHOKE-DLW21S-4P
L13 = L3_2X2_5-3_2
LED6 LED7 = LED19-123-Y2ST1D-C30-2T-4P
MR6 = SOT23_123-2_8-1_9
PC6 PC51 PC74 PC80 PC92 = ECAP6_3X6_1-7_2
PD6 = D-DO-214AC
PJ6 = DCJK-2DC2003-000111-3P-V
PJ7 = 50458-00801-V02-8P-L
PL6 PL7 = CHOKE-PCMC063T-R82MN-4P-SMT
PL8-PL13 = CHOKE-PCMC063T-3R3MN-SMT
PL14 = L3_2X2_5-1_55
PQ2 PQ11-PQ15 PQ17 PQ18 PQ21-PQ23 PQ25 PQ26 PQ28-PQ31 PQ35-PQ38 Q8 Q11 Q12 Q14 Q15 Q17-Q20 Q25 Q27 Q28 Q30 Q33 Q34 Q36 Q41 Q42 Q45 = SOT23_213-3_3-2
PQ6 PQ7 = POWER-5X6-1_27-7P
PQ8 PQ9 PQ16 PQ34 = WDFN5-3_05X3_05-65
PQ10 = TO252_134-9_9-4_57-SMT
PQ20 PQ24 PQ27 PQ33 Q13 Q35 Q39 = UMT_213-3-1_3
PR11 PR54 PR62 PR169 R106 R107 R148 R149 R188-R191 R313 R332 R346 R360 R390 = SHORT0603
PR22 PR23 R207 R278 R340 R341 R402 R407 R427 = SHORT0805
PR26 PR35 PR38 PR42 PR44 PR49 PR50 PR57 PR58 PR66-PR68 PR70 PR72 PR73 PR78 PR86 PR93 PR97 PR100 PR105 PR107 PR110 PR114 PR123 PR126 PR128 PR132 PR133 PR141 PR144 PR145 PR147 PR152 PR154 PR155 PR159 PR161-PR164 PR175-PR177 PR181 PR183 R17 R18 R21 R23 R25 R26 R29 R32 R34 R36 R40 R46 R47 R50 R56 R83 R116 R120-R122 R130 R131 R134 R139 R159 R173 R197 R238 R240 R244 R252 R257 R272 R275 R277 R281-R283 R287 R288 R290 R294 R309 R315 R321 R325 R326 R331 R333-R335 R350 R352 R372 R373 R375 R516 R535 = SHORT0402
PR55 PR71 = F3_2X1_65-2_8
PR101 PR125 PR127 PR135 R33 R37 R224-R228 R411 = RC0805
PU6 PU7 = DFN10-3X3-5-11P-SYF554DBC
PU8 PU10 = QFN14-3X3-4-16P
PU9 PU16 = TQFN20-3X3-4-21P
PU11 = VQFN40-5X5-4-57P
PU12 = QFN32-4X4-4-33P-ISL95812HRZ-SMT
PU13 = TSOP6-2_8-95
PU14 = SOP8-6-1_27-9P
PU15 = SOIC8-6-1_27
Q6 Q7 Q16 Q21 Q23 Q24 Q29 Q32 Q40 Q46 Q50 Q51 Q53 U24 = SC70-2_1-65-6P
RP6 = 10P8R
SW6 SW8 = SW-NTC031-AB1G-A160T-4P
TP6 TP8 TP9 TP15-TP17 TP21-TP26 TP35 TP54-TP59 = TP2050
TP18-TP20 TP27 TP31-TP34 TP36 TP38 TP40 TP41 TP43-TP45 TP48-TP53 = TP2650
TP99-TP101 = TP2675
U3 = MIC-FM-M201-U03-6P
U7 = MSOP8-4_9-65
U8 = TRF-9_4-1_27-24P
U9 = QFN48-6X6-4-49P-ALC280
U11 = QFN32-4X4-4-33P-0_9H
U12 = BGA1170-INTEL-BAY-TRAIL
U13 = QFN28-5X5-5-29P-GL850G
U16 = TSSOP28-6_4-65-SLB9635TT
U18 = LQFP128-16X16-4
U19 = SOT23-5-2_8-95-5P-1_3H
U21 = SOT23-2_8-95-6P
U22 = SOIC8-7_9-1_27
U25 U26 = SC70-2_1-65-6P-0_95H
U27 = VSSOP8-3_1-5-8P
U30 = BGA169-SANDISK-SDIN5C-32G
Y6 Y8 = XTL-3_2X2_5-2_2X1_7
Y7 = XTL-3_2X1_5-2_5-0_8H
Y9 = XTL-3_2X2_5-2_2X1_8-4P

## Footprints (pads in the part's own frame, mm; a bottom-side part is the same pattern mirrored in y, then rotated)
8P4R
  rect 0.406x1.092 smd: 1(-1.194,-0.8) 2(-1.194,0.8) 3(-0.406,-0.8) 4(-0.406,0.8) 5(0.406,-0.8) 6(0.406,0.8) 7(1.194,-0.8) 8(1.194,0.8)
10P8R
  rect 0.305x1.092 smd: 1(-1.27,-0.85) 2(-0.635,-0.85) 3(0,-0.85) 4(0.635,-0.85) 5(1.27,-0.85) 6(1.27,0.85) 7(0.635,0.85) 8(0,0.85) 9(-0.635,0.85) 10(-1.27,0.85)
50458-00801-V02-8P-L
  rect 0.559x1.295 smd: 1(-7,5.025) 2(-5,5.025) 3(-3,5.025) 4(-1,5.025) 5(1,5.025) 6(3,5.025) 7(5,5.025) 8(7,5.025)
  rect 1.295x2.057 smd: 9(-10.1,0) 10(10.1,0)
85208-24071-24P-L
  rect 0.61x1.092 smd: 1(-11.5,3.9) 2(-10.5,3.9) 3(-9.5,3.9) 4(-8.5,3.9) 5(-7.5,3.9) 6(-6.5,3.9) 7(-5.5,3.9) 8(-4.5,3.9) 9(-3.5,3.9) 10(-2.5,3.9) 11(-1.5,3.9) 12(-0.5,3.9) 13(0.5,3.9) 14(1.5,3.9) 15(2.5,3.9) 16(3.5,3.9) 17(4.5,3.9) 18(5.5,3.9) 19(6.5,3.9) 20(7.5,3.9) 21(8.5,3.9) 22(9.5,3.9) 23(10.5,3.9) 24(11.5,3.9)
  custom 0.6x0.6 smd: 25(-14.1,1.7) 26(14.1,1.7)
88266-040XX-XXX-4P-L
  rect 0.787x2.007 smd: 1(-1.875,4.05) 2(-0.625,4.05) 3(0.625,4.05) 4(1.875,4.05)
  rect 2.007x2.489 smd: 5(-4.075,0) 6(4.075,0)
88513-0801-8P-L
  rect 0.508x1.295 smd: 1(-3.5,0) 2(-2.5,0) 3(-1.5,0) 4(-0.5,0) 5(0.5,0) 6(1.5,0) 7(2.5,0) 8(3.5,0)
  rect 1.803x1.397 smd: 9(-5.65,-2.8) 10(5.65,-2.8)
BGA169-SANDISK-SDIN5C-32G
  round 0.279 smd: A4(-1.75,6.75) A6(-0.75,6.75) A9(0.75,6.75) A11(1.75,6.75) AA1(-3.25,-3.25) AA2(-2.75,-3.25) AA3(-2.25,-3.25) AA4(-1.75,-3.25) AA5(-1.25,-3.25) AA6(-0.75,-3.25) AA7(-0.25,-3.25) AA8(0.25,-3.25) AA9(0.75,-3.25) AA10(1.25,-3.25) AA11(1.75,-3.25) AA12(2.25,-3.25) AA13(2.75,-3.25) AA14(3.25,-3.25) AE1(-3.25,-5.25) AE14(3.25,-5.25) AG2(-2.75,-6.25) AG13(2.75,-6.25) AH4(-1.75,-6.75) AH6(-0.75,-6.75) AH9(0.75,-6.75) AH11(1.75,-6.75) B2(-2.75,6.25) B13(2.75,6.25) D1(-3.25,5.25) D14(3.25,5.25) H1(-3.25,3.25) H2(-2.75,3.25) H3(-2.25,3.25) H4(-1.75,3.25) H5(-1.25,3.25) H6(-0.75,3.25) H7(-0.25,3.25) H8(0.25,3.25) H9(0.75,3.25) H10(1.25,3.25) H11(1.75,3.25) H12(2.25,3.25) H13(2.75,3.25) H14(3.25,3.25) J1(-3.25,2.75) J2(-2.75,2.75) J3(-2.25,2.75) J4(-1.75,2.75) J5(-1.25,2.75) J6(-0.75,2.75) J7(-0.25,2.75) J8(0.25,2.75) J9(0.75,2.75) J10(1.25,2.75) J11(1.75,2.75) J12(2.25,2.75) J13(2.75,2.75) J14(3.25,2.75) K1(-3.25,2.25) K2(-2.75,2.25) K3(-2.25,2.25) K4(-1.75,2.25) K5(-1.25,2.25) K6(-0.75,2.25) K7(-0.25,2.25) K8(0.25,2.25) K9(0.75,2.25) K10(1.25,2.25) K11(1.75,2.25) K12(2.25,2.25) K13(2.75,2.25) K14(3.25,2.25) L1(-3.25,1.75) L2(-2.75,1.75) L3(-2.25,1.75) L4(-1.75,1.75) L12(2.25,1.75) L13(2.75,1.75) L14(3.25,1.75) M1(-3.25,1.25) M2(-2.75,1.25) M3(-2.25,1.25) M5(-1.25,1.25) M6(-0.75,1.25) M7(-0.25,1.25) M8(0.25,1.25) M9(0.75,1.25) M10(1.25,1.25) M12(2.25,1.25) M13(2.75,1.25) M14(3.25,1.25) N1(-3.25,0.75) N2(-2.75,0.75) N3(-2.25,0.75) N5(-1.25,0.75) N10(1.25,0.75) N12(2.25,0.75) N13(2.75,0.75) N14(3.25,0.75) P1(-3.25,0.25) P2(-2.75,0.25) P3(-2.25,0.25) P5(-1.25,0.25) P10(1.25,0.25) P12(2.25,0.25) P13(2.75,0.25) P14(3.25,0.25) R1(-3.25,-0.25) R2(-2.75,-0.25) R3(-2.25,-0.25) R5(-1.25,-0.25) R10(1.25,-0.25) R12(2.25,-0.25) R13(2.75,-0.25) R14(3.25,-0.25) T1(-3.25,-0.75) T2(-2.75,-0.75) T3(-2.25,-0.75) T5(-1.25,-0.75) T10(1.25,-0.75) T12(2.25,-0.75) T13(2.75,-0.75) T14(3.25,-0.75) U1(-3.25,-1.25) U2(-2.75,-1.25) U3(-2.25,-1.25) U5(-1.25,-1.25) U6(-0.75,-1.25) U7(-0.25,-1.25) U8(0.25,-1.25) U9(0.75,-1.25) U10(1.25,-1.25) U12(2.25,-1.25) U13(2.75,-1.25) U14(3.25,-1.25) V1(-3.25,-1.75) V2(-2.75,-1.75) V3(-2.25,-1.75) V12(2.25,-1.75) V13(2.75,-1.75) V14(3.25,-1.75) W1(-3.25,-2.25) W2(-2.75,-2.25) W3(-2.25,-2.25) W4(-1.75,-2.25) W5(-1.25,-2.25) W6(-0.75,-2.25) W7(-0.25,-2.25) W8(0.25,-2.25) W9(0.75,-2.25) W10(1.25,-2.25) W11(1.75,-2.25) W12(2.25,-2.25) W13(2.75,-2.25) W14(3.25,-2.25) Y1(-3.25,-2.75) Y2(-2.75,-2.75) Y3(-2.25,-2.75) Y4(-1.75,-2.75) Y5(-1.25,-2.75) Y6(-0.75,-2.75) Y7(-0.25,-2.75) Y8(0.25,-2.75) Y9(0.75,-2.75) Y10(1.25,-2.75) Y11(1.75,-2.75) Y12(2.25,-2.75) Y13(2.75,-2.75) Y14(3.25,-2.75)
BGA1170-INTEL-BAY-TRAIL
  round 0.521 smd: A3(-11.814,-11.951) A52(-11.814,12.383) B2(-11.383,-12.383) B53(-11.383,12.814) BH1(11.383,-12.814) BH53(11.383,12.814) BJ2(11.814,-12.383) BJ52(11.814,12.383) C1(-10.951,-12.814)
  round 0.406 smd: A5(-11.814,-11.17) A6(-11.814,-10.447) A49(-11.814,10.992) A51(-11.814,11.773) B52(-11.225,12.225) BE1(9.992,-12.814) BE53(9.992,12.814) BG1(10.773,-12.814) BG53(10.773,12.814) BH2(11.225,-12.225) BH52(11.225,12.225) BJ3(11.814,-11.773) BJ5(11.814,-10.992) BJ49(11.814,10.992) BJ51(11.814,11.773) C53(-10.773,12.814) E1(-10.17,-12.814) E53(-9.992,12.814) F1(-9.447,-12.814)
  round 0.356 smd: A7(-11.814,-9.748) A9(-11.814,-8.836) A47(-11.814,9.621) A48(-11.814,10.294) B4(-11.238,-11.632) B5(-11.222,-11.038) B6(-11.221,-10.445) B8(-11.224,-9.258) B46(-11.224,9.258) B48(-11.221,10.445) B49(-11.222,11.038) B50(-11.238,11.632) BC1(8.621,-12.814) BC2(8.852,-12.246) BC52(8.852,12.246) BC53(8.621,12.814) BD1(9.294,-12.814) BD2(9.445,-12.221) BD52(9.445,12.221) BD53(9.294,12.814) BE2(10.038,-12.222) BE52(10.038,12.222) BF2(10.632,-12.238) BF52(10.632,12.238) BG3(10.644,-11.644) BG51(10.644,11.644) BH4(11.238,-11.632) BH5(11.222,-11.038) BH6(11.221,-10.445) BH8(11.224,-9.258) BH46(11.224,9.258) BH48(11.221,10.445) BH49(11.222,11.038) BH50(11.238,11.632) BJ6(11.814,-10.294) BJ7(11.814,-9.621) BJ47(11.814,9.621) BJ48(11.814,10.294) C3(-10.644,-11.644) C51(-10.644,11.644) D2(-10.632,-12.238) D52(-10.632,12.238) E2(-10.038,-12.222) E52(-10.038,12.222) F2(-9.445,-12.221) F52(-9.445,12.221) F53(-9.294,12.814) G1(-8.679,-12.814) G2(-8.852,-12.246) G52(-8.852,12.246) G53(-8.621,12.814) J1(-7.816,-12.814)
  custom 0.064x0.064 smd: A11(-11.814,-7.774) A13(-11.814,-6.803) A15(-11.814,-5.831) A17(-11.814,-4.859) A19(-11.814,-3.887) A21(-11.814,-2.915) A23(-11.814,-1.944) A25(-11.814,-0.972) A27(-11.814,0) A29(-11.814,0.972) A31(-11.814,1.944) A33(-11.814,2.915) A35(-11.814,3.887) A37(-11.814,4.859) A39(-11.814,5.831) A41(-11.814,6.803) A43(-11.814,7.774) A45(-11.814,8.746) BJ9(11.814,-8.746) BJ11(11.814,-7.774) BJ13(11.814,-6.803) BJ15(11.814,-5.831) BJ17(11.814,-4.859) BJ19(11.814,-3.887) BJ21(11.814,-2.915) BJ23(11.814,-1.944) BJ25(11.814,-0.972) BJ27(11.814,0) BJ29(11.814,0.972) BJ31(11.814,1.944) BJ33(11.814,2.915) BJ35(11.814,3.887) BJ37(11.814,4.859) BJ39(11.814,5.831) BJ41(11.814,6.803) BJ43(11.814,7.774) BJ45(11.814,8.746)
  oval 0.254x0.343 smd: AA1(-1.944,-12.814) AA53(-1.944,12.814) AC1(-0.972,-12.814) AC53(-0.972,12.814) AE1(0,-12.814) AE53(0,12.814) AG1(0.972,-12.814) AG53(0.972,12.814) AJ1(1.944,-12.814) AJ53(1.944,12.814) AL1(2.915,-12.814) AL53(2.915,12.814) AN1(3.887,-12.814) AN53(3.887,12.814) AR1(4.859,-12.814) AR53(4.859,12.814) AU1(5.831,-12.814) AU53(5.831,12.814) AW1(6.803,-12.814) AW53(6.803,12.814) BA1(7.774,-12.814) BA53(7.774,12.814) J53(-7.774,12.814) L1(-6.803,-12.814) L53(-6.803,12.814) N1(-5.831,-12.814) N53(-5.831,12.814) R1(-4.859,-12.814) R53(-4.859,12.814) U1(-3.887,-12.814) U53(-3.887,12.814) W1(-2.915,-12.814) W53(-2.915,12.814)
  round 0.279 smd: AA3(-1.944,-12.071) AA51(-1.944,12.071) AB2(-1.458,-12.429) AB3(-1.458,-11.73) AB51(-1.458,11.73) AB52(-1.458,12.429) AC3(-0.972,-12.071) AC51(-0.972,12.071) AD2(-0.486,-12.429) AD3(-0.48,-11.715) AD51(-0.48,11.715) AD52(-0.486,12.429) AE3(0,-12.071) AE4(0,-11.366) AE50(0,11.366) AE51(0,12.071) AF2(0.486,-12.429) AF3(0.48,-11.715) AF51(0.48,11.715) AF52(0.486,12.429) AG3(0.972,-12.071) AG51(0.972,12.071) AH2(1.458,-12.429) AH3(1.458,-11.73) AH51(1.458,11.73) AH52(1.458,12.429) AJ3(1.944,-12.071) AJ51(1.944,12.071) AK2(2.43,-12.429) AK3(2.43,-11.73) AK51(2.43,11.73) AK52(2.43,12.429) AL3(2.915,-12.071) AL51(2.915,12.071) AM2(3.401,-12.429) AM3(3.401,-11.73) AM51(3.401,11.73) AM52(3.401,12.429) AN3(3.887,-12.071) AN51(3.887,12.071) AP2(4.373,-12.429) AP3(4.373,-11.73) AP51(4.373,11.73) AP52(4.373,12.429) AR3(4.859,-12.071) AR51(4.859,12.071) AT2(5.345,-12.429) AT3(5.345,-11.73) AT51(5.345,11.73) AT52(5.345,12.429) AU3(5.831,-12.071) AU51(5.831,12.071) AV2(6.317,-12.429) AV3(6.317,-11.73) AV51(6.317,11.73) AV52(6.317,12.429) AW3(6.803,-12.071) AW51(6.803,12.071) AY2(7.289,-12.429) AY3(7.289,-11.73) AY51(7.289,11.73) AY52(7.289,12.429) B10(-11.429,-8.26) B12(-11.429,-7.289) B14(-11.429,-6.317) B16(-11.429,-5.345) B18(-11.429,-4.373) B20(-11.429,-3.401) B22(-11.429,-2.43) B24(-11.429,-1.458) B26(-11.429,-0.486) B28(-11.429,0.486) B30(-11.429,1.458) B32(-11.429,2.43) B34(-11.429,3.401) B36(-11.429,4.373) B38(-11.429,5.345) B40(-11.429,6.317) B42(-11.429,7.289) B44(-11.429,8.26) BA3(7.774,-12.071) BA51(7.774,12.071) BB3(8.351,-11.929) BB51(8.351,11.929) BF27(10.366,0) BG9(11.028,-8.698) BG11(11.071,-7.774) BG12(10.73,-7.289) BG13(11.071,-6.803) BG14(10.73,-6.317) BG15(11.071,-5.831) BG16(10.73,-5.345) BG17(11.071,-4.859) BG18(10.73,-4.373) BG19(11.071,-3.887) BG20(10.73,-3.401) BG21(11.071,-2.915) BG22(10.73,-2.43) BG23(11.071,-1.944) BG24(10.73,-1.458) BG25(11.071,-0.972) BG26(10.715,-0.48) BG27(11.071,0) BG28(10.715,0.48) BG29(11.071,0.972) BG30(10.73,1.458) BG31(11.071,1.944) BG32(10.73,2.43) BG33(11.071,2.915) BG34(10.73,3.401) BG35(11.071,3.887) BG36(10.73,4.373) BG37(11.071,4.859) BG38(10.73,5.345) BG39(11.071,5.831) BG40(10.73,6.317) BG41(11.071,6.803) BG42(10.73,7.289) BG43(11.071,7.774) BG45(11.028,8.698) BH10(11.429,-8.26) BH12(11.429,-7.289) BH14(11.429,-6.317) BH16(11.429,-5.345) BH18(11.429,-4.373) BH20(11.429,-3.401) BH22(11.429,-2.43) BH24(11.429,-1.458) BH26(11.429,-0.486) BH28(11.429,0.486) BH30(11.429,1.458) BH32(11.429,2.43) BH34(11.429,3.401) BH36(11.429,4.373) BH38(11.429,5.345) BH40(11.429,6.317) BH42(11.429,7.289) BH44(11.429,8.26) C9(-11.028,-8.698) C11(-11.071,-7.774) C12(-10.73,-7.289) C13(-11.071,-6.803) C14(-10.73,-6.317) C15(-11.071,-5.831) C16(-10.73,-5.345) C17(-11.071,-4.859) C18(-10.73,-4.373) C19(-11.071,-3.887) C20(-10.73,-3.401) C21(-11.071,-2.915) C22(-10.73,-2.43) C23(-11.071,-1.944) C24(-10.73,-1.458) C25(-11.071,-0.972) C26(-10.715,-0.48) C27(-11.071,0) C28(-10.715,0.48) C29(-11.071,0.972) C30(-10.73,1.458) C31(-11.071,1.944) C32(-10.73,2.43) C33(-11.071,2.915) C34(-10.73,3.401) C35(-11.071,3.887) C36(-10.73,4.373) C37(-11.071,4.859) C38(-10.73,5.345) C39(-11.071,5.831) C40(-10.73,6.317) C41(-11.071,6.803) C42(-10.73,7.289) C43(-11.071,7.774) C45(-11.028,8.698) D27(-10.366,0) H3(-8.351,-11.929) H51(-8.351,11.929) J3(-7.774,-12.071) J51(-7.774,12.071) K2(-7.289,-12.429) K3(-7.289,-11.73) K51(-7.289,11.73) K52(-7.289,12.429) L3(-6.803,-12.071) L51(-6.803,12.071) M2(-6.317,-12.429) M3(-6.317,-11.73) M51(-6.317,11.73) M52(-6.317,12.429) N3(-5.831,-12.071) N51(-5.831,12.071) P2(-5.345,-12.429) P3(-5.345,-11.73) P51(-5.345,11.73) P52(-5.345,12.429) R3(-4.859,-12.071) R51(-4.859,12.071) T2(-4.373,-12.429) T3(-4.373,-11.73) T51(-4.373,11.73) T52(-4.373,12.429) U3(-3.887,-12.071) U51(-3.887,12.071) V2(-3.401,-12.429) V3(-3.401,-11.73) V51(-3.401,11.73) V52(-3.401,12.429) W3(-2.915,-12.071) W51(-2.915,12.071) Y2(-2.43,-12.429) Y3(-2.43,-11.73) Y51(-2.43,11.73) Y52(-2.43,12.429)
  round 0.33 smd: AA16(-1.961,-5.307) AA18(-1.961,-4.549) AA19(-1.961,-3.791) AA21(-1.961,-3.033) AA22(-1.961,-2.275) AA24(-1.961,-1.516) AA25(-1.961,-0.758) AA27(-1.961,0) AA29(-1.961,0.758) AA30(-1.961,1.516) AA32(-1.961,2.275) AA33(-1.961,3.033) AA35(-1.961,3.791) AA36(-1.961,4.549) AA38(-1.961,5.307) AC16(-1.177,-5.307) AC18(-1.177,-4.549) AC19(-1.177,-3.791) AC21(-1.177,-3.033) AC22(-1.177,-2.275) AC24(-1.177,-1.516) AC25(-1.177,-0.758) AC27(-1.177,0) AC29(-1.177,0.758) AC30(-1.177,1.516) AC32(-1.177,2.275) AC33(-1.177,3.033) AC35(-1.177,3.791) AC36(-1.177,4.549) AC38(-1.177,5.307) AD16(-0.392,-5.307) AD18(-0.392,-4.549) AD19(-0.392,-3.791) AD21(-0.392,-3.033) AD22(-0.392,-2.275) AD24(-0.392,-1.516) AD25(-0.392,-0.758) AD27(-0.392,0) AD29(-0.392,0.758) AD30(-0.392,1.516) AD32(-0.392,2.275) AD33(-0.392,3.033) AD35(-0.392,3.791) AD36(-0.392,4.549) AD38(-0.392,5.307) AF16(0.392,-5.307) AF18(0.392,-4.549) AF19(0.392,-3.791) AF21(0.392,-3.033) AF22(0.392,-2.275) AF24(0.392,-1.516) AF25(0.392,-0.758) AF27(0.392,0) AF29(0.392,0.758) AF30(0.392,1.516) AF32(0.392,2.275) AF33(0.392,3.033) AF35(0.392,3.791) AF36(0.392,4.549) AF38(0.392,5.307) AG16(1.177,-5.307) AG18(1.177,-4.549) AG19(1.177,-3.791) AG21(1.177,-3.033) AG22(1.177,-2.275) AG24(1.177,-1.516) AG25(1.177,-0.758) AG27(1.177,0) AG29(1.177,0.758) AG30(1.177,1.516) AG32(1.177,2.275) AG33(1.177,3.033) AG35(1.177,3.791) AG36(1.177,4.549) AG38(1.177,5.307) AJ16(1.961,-5.307) AJ18(1.961,-4.549) AJ19(1.961,-3.791) AJ21(1.961,-3.033) AJ22(1.961,-2.275) AJ24(1.961,-1.516) AJ25(1.961,-0.758) AJ27(1.961,0) AJ29(1.961,0.758) AJ30(1.961,1.516) AJ32(1.961,2.275) AJ33(1.961,3.033) AJ35(1.961,3.791) AJ36(1.961,4.549) AJ38(1.961,5.307) AK16(2.745,-5.307) AK18(2.745,-4.549) AK19(2.745,-3.791) AK21(2.745,-3.033) AK22(2.745,-2.275) AK24(2.745,-1.516) AK25(2.745,-0.758) AK27(2.745,0) AK29(2.745,0.758) AK30(2.745,1.516) AK32(2.745,2.275) AK33(2.745,3.033) AK35(2.745,3.791) AK36(2.745,4.549) AK38(2.745,5.307) AM16(3.53,-5.307) AM18(3.53,-4.549) AM19(3.53,-3.791) AM21(3.53,-3.033) AM22(3.53,-2.275) AM24(3.53,-1.516) AM25(3.53,-0.758) AM27(3.53,0) AM29(3.53,0.758) AM30(3.53,1.516) AM32(3.53,2.275) AM33(3.53,3.033) AM35(3.53,3.791) AM36(3.53,4.549) AM38(3.53,5.307) AN16(4.314,-5.307) AN18(4.314,-4.549) AN19(4.314,-3.791) AN21(4.314,-3.033) AN22(4.314,-2.275) AN24(4.314,-1.516) AN25(4.314,-0.758) AN27(4.314,0) AN29(4.314,0.758) AN30(4.314,1.516) AN32(4.314,2.275) AN33(4.314,3.033) AN35(4.314,3.791) AN36(4.314,4.549) AN38(4.314,5.307) U16(-4.314,-5.307) U18(-4.314,-4.549) U19(-4.314,-3.791) U21(-4.314,-3.033) U22(-4.314,-2.275) U24(-4.314,-1.516) U25(-4.314,-0.758) U27(-4.314,0) U29(-4.314,0.758) U30(-4.314,1.516) U32(-4.314,2.275) U33(-4.314,3.033) U35(-4.314,3.791) U36(-4.314,4.549) U38(-4.314,5.307) V16(-3.53,-5.307) V18(-3.53,-4.549) V19(-3.53,-3.791) V21(-3.53,-3.033) V22(-3.53,-2.275) V24(-3.53,-1.516) V25(-3.53,-0.758) V27(-3.53,0) V29(-3.53,0.758) V30(-3.53,1.516) V32(-3.53,2.275) V33(-3.53,3.033) V35(-3.53,3.791) V36(-3.53,4.549) V38(-3.53,5.307) Y16(-2.745,-5.307) Y18(-2.745,-4.549) Y19(-2.745,-3.791) Y21(-2.745,-3.033) Y22(-2.745,-2.275) Y24(-2.745,-1.516) Y25(-2.745,-0.758) Y27(-2.745,0) Y29(-2.745,0.758) Y30(-2.745,1.516) Y32(-2.745,2.275) Y33(-2.745,3.033) Y35(-2.745,3.791) Y36(-2.745,4.549) Y38(-2.745,5.307)
  round 0.305 smd: AB4(-1.448,-11.137) AB6(-1.448,-10.463) AB7(-1.448,-9.752) AB9(-1.448,-9.041) AB10(-1.448,-8.33) AB12(-1.448,-7.618) AB13(-1.448,-6.907) AB14(-1.448,-6.196) AB40(-1.448,6.196) AB41(-1.448,6.907) AB42(-1.448,7.618) AB44(-1.448,8.33) AB45(-1.448,9.041) AB47(-1.448,9.752) AB48(-1.448,10.463) AB50(-1.448,11.137) AD4(-0.463,-10.995) AD6(-0.525,-10.404) AD7(-0.475,-9.752) AD9(-0.475,-9.041) AD10(-0.475,-8.33) AD12(-0.475,-7.618) AD13(-0.475,-6.907) AD14(-0.475,-6.196) AD40(-0.475,6.196) AD41(-0.475,6.907) AD42(-0.475,7.618) AD44(-0.475,8.33) AD45(-0.475,9.041) AD47(-0.475,9.752) AD48(-0.525,10.404) AD50(-0.463,10.995) AE6(0,-10.108) AE8(0,-9.396) AE9(0,-8.685) AE11(0,-7.974) AE12(0,-7.263) AE14(0,-6.552) AE40(0,6.552) AE42(0,7.263) AE43(0,7.974) AE45(0,8.685) AE46(0,9.396) AE48(0,10.108) AF4(0.463,-10.995) AF6(0.525,-10.404) AF7(0.475,-9.752) AF9(0.475,-9.041) AF10(0.475,-8.33) AF12(0.475,-7.618) AF13(0.475,-6.907) AF14(0.475,-6.196) AF40(0.475,6.196) AF41(0.475,6.907) AF42(0.475,7.618) AF44(0.475,8.33) AF45(0.475,9.041) AF47(0.475,9.752) AF48(0.525,10.404) AF50(0.463,10.995) AH4(1.448,-11.137) AH6(1.448,-10.463) AH7(1.448,-9.752) AH9(1.448,-9.041) AH10(1.448,-8.33) AH12(1.448,-7.618) AH13(1.448,-6.907) AH14(1.448,-6.196) AH40(1.448,6.196) AH41(1.448,6.907) AH42(1.448,7.618) AH44(1.448,8.33) AH45(1.448,9.041) AH47(1.448,9.752) AH48(1.448,10.463) AH50(1.448,11.137) AK4(2.439,-11.137) AK6(2.439,-10.463) AK7(2.439,-9.752) AK9(2.439,-9.041) AK10(2.439,-8.33) AK12(2.439,-7.618) AK13(2.439,-6.907) AK14(2.439,-6.196) AK40(2.439,6.196) AK41(2.439,6.907) AK42(2.439,7.618) AK44(2.439,8.33) AK45(2.439,9.041) AK47(2.439,9.752) AK48(2.439,10.463) AK50(2.439,11.137) AM4(3.386,-11.137) AM6(3.412,-10.463) AM7(3.412,-9.752) AM9(3.412,-9.041) AM10(3.412,-8.33) AM12(3.412,-7.618) AM13(3.412,-6.907) AM14(3.412,-6.196) AM40(3.412,6.196) AM41(3.412,6.907) AM42(3.412,7.618) AM44(3.412,8.33) AM45(3.412,9.041) AM47(3.412,9.752) AM48(3.412,10.463) AM50(3.386,11.137) AN5(3.887,-10.819) AN6(3.887,-10.108) AN8(3.887,-9.396) AN9(3.887,-8.685) AN11(3.887,-7.974) AN12(3.887,-7.263) AN14(3.887,-6.552) AN40(3.887,6.552) AN42(3.887,7.263) AN43(3.887,7.974) AN45(3.887,8.685) AN46(3.887,9.396) AN48(3.887,10.108) AN49(3.887,10.819) AP4(4.388,-11.137) AP6(4.362,-10.463) AP7(4.362,-9.752) AP9(4.362,-9.041) AP10(4.362,-8.33) AP12(4.362,-7.618) AP13(4.362,-6.907) AP14(4.362,-6.196) AP40(4.362,6.196) AP41(4.362,6.907) AP42(4.362,7.618) AP44(4.362,8.33) AP45(4.362,9.041) AP47(4.362,9.752) AP48(4.362,10.463) AP50(4.388,11.137) AT4(5.336,-11.137) AT6(5.336,-10.463) AT7(5.336,-9.752) AT9(5.336,-9.041) AT10(5.336,-8.33) AT12(5.336,-7.618) AT13(5.336,-6.907) AT14(5.336,-6.305) AT16(5.196,-5.336) AT18(5.196,-4.362) AT19(5.552,-3.887) AT20(5.196,-3.412) AT22(5.196,-2.439) AT24(5.196,-1.448) AT26(5.196,-0.475) AT27(5.552,0) AT28(5.196,0.475) AT30(5.196,1.448) AT32(5.196,2.439) AT34(5.196,3.412) AT35(5.552,3.887) AT36(5.196,4.362) AT38(5.196,5.336) AT40(5.336,6.305) AT41(5.336,6.907) AT42(5.336,7.618) AT44(5.336,8.33) AT45(5.336,9.041) AT47(5.336,9.752) AT48(5.336,10.463) AT50(5.336,11.137) AU16(5.907,-5.336) AU18(5.907,-4.362) AU20(5.907,-3.412) AU22(5.907,-2.439) AU24(5.907,-1.448) AU26(5.907,-0.475) AU28(5.907,0.475) AU30(5.907,1.448) AU32(5.907,2.439) AU34(5.907,3.412) AU36(5.907,4.362) AU38(5.907,5.336) AV4(6.326,-11.137) AV6(6.326,-10.463) AV7(6.326,-9.752) AV9(6.326,-9.041) AV10(6.326,-8.33) AV12(6.326,-7.618) AV13(6.326,-6.907) AV14(6.446,-6.326) AV16(6.618,-5.336) AV18(6.618,-4.362) AV19(6.263,-3.887) AV20(6.618,-3.412) AV22(6.618,-2.439) AV24(6.618,-1.448) AV26(6.618,-0.475) AV27(6.263,0) AV28(6.618,0.475) AV30(6.618,1.448) AV32(6.618,2.439) AV34(6.618,3.412) AV35(6.263,3.887) AV36(6.618,4.362) AV38(6.618,5.336) AV40(6.446,6.326) AV41(6.326,6.907) AV42(6.326,7.618) AV44(6.326,8.33) AV45(6.326,9.041) AV47(6.326,9.752) AV48(6.326,10.463) AV50(6.326,11.137) AW13(6.915,-6.751) AW19(6.974,-3.887) AW27(6.974,0) AW35(6.974,3.887) AW41(6.915,6.751) AY4(7.317,-11.137) AY6(7.317,-10.463) AY7(7.317,-9.752) AY9(7.317,-9.041) AY10(7.317,-8.33) AY12(7.34,-7.317) AY14(7.33,-6.326) AY16(7.33,-5.336) AY18(7.33,-4.362) AY20(7.33,-3.412) AY22(7.33,-2.439) AY24(7.33,-1.448) AY26(7.33,-0.475) AY28(7.33,0.475) AY30(7.33,1.448) AY32(7.33,2.439) AY34(7.33,3.412) AY36(7.33,4.362) AY38(7.33,5.336) AY40(7.33,6.326) AY42(7.34,7.317) AY44(7.317,8.33) AY45(7.317,9.041) AY47(7.317,9.752) AY48(7.317,10.463) AY50(7.317,11.137) B7(-11.23,-9.852) B47(-11.23,9.852) BA12(8.041,-7.317) BA14(8.041,-6.326) BA16(8.041,-5.336) BA18(8.041,-4.362) BA19(7.685,-3.887) BA20(8.041,-3.412) BA22(8.041,-2.439) BA24(8.041,-1.448) BA26(8.041,-0.475) BA27(7.685,0) BA28(8.041,0.475) BA30(8.041,1.448) BA32(8.041,2.439) BA34(8.041,3.412) BA35(7.685,3.887) BA36(8.041,4.362) BA38(8.041,5.336) BA40(8.041,6.326) BA42(8.041,7.317) BB4(8.307,-11.258) BB5(8.307,-10.547) BB7(8.307,-9.835) BB8(8.307,-9.124) BB10(8.17,-8.307) BB19(8.396,-3.887) BB27(8.396,0) BB35(8.396,3.887) BB44(8.17,8.307) BB46(8.307,9.124) BB47(8.307,9.835) BB49(8.307,10.547) BB50(8.307,11.258) BC10(8.764,-8.307) BC12(8.752,-7.317) BC14(8.752,-6.326) BC16(8.752,-5.336) BC18(8.752,-4.362) BC20(8.752,-3.412) BC22(8.752,-2.439) BC24(8.752,-1.448) BC26(8.752,-0.475) BC28(8.752,0.475) BC30(8.752,1.448) BC32(8.752,2.439) BC34(8.752,3.412) BC36(8.752,4.362) BC38(8.752,5.336) BC40(8.752,6.326) BC42(8.752,7.317) BC44(8.764,8.307) BD5(9.302,-10.565) BD7(9.302,-9.712) BD10(9.457,-8.307) BD12(9.463,-7.317) BD14(9.463,-6.326) BD16(9.463,-5.336) BD18(9.463,-4.362) BD19(9.108,-3.887) BD20(9.463,-3.412) BD22(9.463,-2.439) BD24(9.463,-1.448) BD26(9.404,-0.525) BD27(9.108,0) BD28(9.404,0.525) BD30(9.463,1.448) BD32(9.463,2.439) BD34(9.463,3.412) BD35(9.108,3.887) BD36(9.463,4.362) BD38(9.463,5.336) BD40(9.463,6.326) BD42(9.463,7.317) BD44(9.457,8.307) BD47(9.302,9.712) BD49(9.302,10.565) BE3(9.58,-11.643) BE8(9.747,-9.32) BE19(9.819,-3.887) BE35(9.819,3.887) BE46(9.747,9.32) BE51(9.58,11.643) BF4(10.163,-11.163) BF6(10.238,-10.113) BF10(10.168,-8.307) BF12(10.137,-7.317) BF14(10.137,-6.326) BF16(10.137,-5.336) BF18(10.137,-4.388) BF20(10.137,-3.386) BF22(10.137,-2.439) BF24(10.137,-1.448) BF26(9.995,-0.463) BF28(9.995,0.463) BF30(10.137,1.448) BF32(10.137,2.439) BF34(10.137,3.386) BF36(10.137,4.388) BF38(10.137,5.336) BF40(10.137,6.326) BF42(10.137,7.317) BF44(10.168,8.307) BF48(10.238,10.113) BF50(10.163,11.163) BG5(10.643,-10.58) BG7(10.709,-9.553) BG47(10.709,9.553) BG49(10.643,10.58) BH7(11.23,-9.852) BH47(11.23,9.852) C5(-10.643,-10.58) C7(-10.709,-9.553) C47(-10.709,9.553) C49(-10.643,10.58) D4(-10.163,-11.163) D6(-10.238,-10.113) D10(-10.168,-8.307) D12(-10.137,-7.317) D14(-10.137,-6.326) D16(-10.137,-5.336) D18(-10.137,-4.388) D20(-10.137,-3.386) D22(-10.137,-2.439) D24(-10.137,-1.448) D26(-9.995,-0.463) D28(-9.995,0.463) D30(-10.137,1.448) D32(-10.137,2.439) D34(-10.137,3.386) D36(-10.137,4.388) D38(-10.137,5.336) D40(-10.137,6.326) D42(-10.137,7.317) D44(-10.168,8.307) D48(-10.238,10.113) D50(-10.163,11.163) E3(-9.58,-11.643) E8(-9.747,-9.32) E19(-9.819,-3.887) E35(-9.819,3.887) E46(-9.747,9.32) E51(-9.58,11.643) F5(-9.302,-10.565) F7(-9.302,-9.712) F10(-9.457,-8.307) F12(-9.463,-7.317) F14(-9.463,-6.326) F16(-9.463,-5.336) F18(-9.463,-4.362) F19(-9.108,-3.887) F20(-9.463,-3.412) F22(-9.463,-2.439) F24(-9.463,-1.448) F26(-9.404,-0.525) F27(-9.108,0) F28(-9.404,0.525) F30(-9.463,1.448) F32(-9.463,2.439) F34(-9.463,3.412) F35(-9.108,3.887) F36(-9.463,4.362) F38(-9.463,5.336) F40(-9.463,6.326) F42(-9.463,7.317) F44(-9.457,8.307) F47(-9.302,9.712) F49(-9.302,10.565) G10(-8.764,-8.307) G12(-8.752,-7.317) G14(-8.752,-6.326) G16(-8.752,-5.336) G18(-8.752,-4.362) G20(-8.752,-3.412) G22(-8.752,-2.439) G24(-8.752,-1.448) G26(-8.752,-0.475) G28(-8.752,0.475) G30(-8.752,1.448) G32(-8.752,2.439) G34(-8.752,3.412) G36(-8.752,4.362) G38(-8.752,5.336) G40(-8.752,6.326) G42(-8.752,7.317) G44(-8.764,8.307) H4(-8.307,-11.258) H5(-8.307,-10.547) H7(-8.307,-9.835) H8(-8.307,-9.124) H10(-8.17,-8.307) H19(-8.396,-3.887) H27(-8.396,0) H35(-8.396,3.887) H44(-8.17,8.307) H46(-8.307,9.124) H47(-8.307,9.835) H49(-8.307,10.547) H50(-8.307,11.258) J12(-8.041,-7.317) J14(-8.041,-6.326) J16(-8.041,-5.336) J18(-8.041,-4.362) J19(-7.685,-3.887) J20(-8.041,-3.412) J22(-8.041,-2.439) J24(-8.041,-1.448) J26(-8.041,-0.475) J27(-7.685,0) J28(-8.041,0.475) J30(-8.041,1.448) J32(-8.041,2.439) J34(-8.041,3.412) J35(-7.685,3.887) J36(-8.041,4.362) J38(-8.041,5.336) J40(-8.041,6.326) J42(-8.041,7.317) K4(-7.317,-11.137) K6(-7.317,-10.463) K7(-7.317,-9.752) K9(-7.317,-9.041) K10(-7.317,-8.33) K12(-7.34,-7.317) K14(-7.33,-6.326) K16(-7.33,-5.336) K18(-7.33,-4.362) K20(-7.33,-3.412) K22(-7.33,-2.439) K24(-7.33,-1.448) K26(-7.33,-0.475) K28(-7.33,0.475) K30(-7.33,1.448) K32(-7.33,2.439) K34(-7.33,3.412) K36(-7.33,4.362) K38(-7.33,5.336) K40(-7.33,6.326) K42(-7.34,7.317) K44(-7.317,8.33) K45(-7.317,9.041) K47(-7.317,9.752) K48(-7.317,10.463) K50(-7.317,11.137) L13(-6.915,-6.751) L19(-6.974,-3.887) L27(-6.974,0) L35(-6.974,3.887) L41(-6.915,6.751) M4(-6.326,-11.137) M6(-6.326,-10.463) M7(-6.326,-9.752) M9(-6.326,-9.041) M10(-6.326,-8.33) M12(-6.326,-7.618) M13(-6.326,-6.907) M14(-6.446,-6.326) M16(-6.618,-5.336) M18(-6.618,-4.362) M19(-6.263,-3.887) M20(-6.618,-3.412) M22(-6.618,-2.439) M24(-6.618,-1.448) M26(-6.618,-0.475) M27(-6.263,0) M28(-6.618,0.475) M30(-6.618,1.448) M32(-6.618,2.439) M34(-6.618,3.412) M35(-6.263,3.887) M36(-6.618,4.362) M38(-6.618,5.336) M40(-6.446,6.326) M41(-6.326,6.907) M42(-6.326,7.618) M44(-6.326,8.33) M45(-6.326,9.041) M47(-6.326,9.752) M48(-6.326,10.463) M50(-6.326,11.137) N16(-5.907,-5.336) N18(-5.907,-4.362) N20(-5.907,-3.412) N22(-5.907,-2.439) N24(-5.907,-1.448) N26(-5.907,-0.475) N28(-5.907,0.475) N30(-5.907,1.448) N32(-5.907,2.439) N34(-5.907,3.412) N36(-5.907,4.362) N38(-5.907,5.336) P4(-5.336,-11.137) P6(-5.336,-10.463) P7(-5.336,-9.752) P9(-5.336,-9.041) P10(-5.336,-8.33) P12(-5.336,-7.618) P13(-5.336,-6.907) P14(-5.336,-6.305) P16(-5.196,-5.336) P18(-5.196,-4.362) P19(-5.552,-3.887) P20(-5.196,-3.412) P22(-5.196,-2.439) P24(-5.196,-1.448) P26(-5.196,-0.475) P27(-5.552,0) P28(-5.196,0.475) P30(-5.196,1.448) P32(-5.196,2.439) P34(-5.196,3.412) P35(-5.552,3.887) P36(-5.196,4.362) P38(-5.196,5.336) P40(-5.336,6.305) P41(-5.336,6.907) P42(-5.336,7.618) P44(-5.336,8.33) P45(-5.336,9.041) P47(-5.336,9.752) P48(-5.336,10.463) P50(-5.336,11.137) T4(-4.388,-11.137) T6(-4.362,-10.463) T7(-4.362,-9.752) T9(-4.362,-9.041) T10(-4.362,-8.33) T12(-4.362,-7.618) T13(-4.362,-6.907) T14(-4.362,-6.196) T40(-4.362,6.196) T41(-4.362,6.907) T42(-4.362,7.618) T44(-4.362,8.33) T45(-4.362,9.041) T47(-4.362,9.752) T48(-4.362,10.463) T50(-4.388,11.137) U5(-3.887,-10.819) U6(-3.887,-10.108) U8(-3.887,-9.396) U9(-3.887,-8.685) U11(-3.887,-7.974) U12(-3.887,-7.263) U14(-3.887,-6.552) U40(-3.887,6.552) U42(-3.887,7.263) U43(-3.887,7.974) U45(-3.887,8.685) U46(-3.887,9.396) U48(-3.887,10.108) U49(-3.887,10.819) V4(-3.386,-11.137) V6(-3.412,-10.463) V7(-3.412,-9.752) V9(-3.412,-9.041) V10(-3.412,-8.33) V12(-3.412,-7.618) V13(-3.412,-6.907) V14(-3.412,-6.196) V40(-3.412,6.196) V41(-3.412,6.907) V42(-3.412,7.618) V44(-3.412,8.33) V45(-3.412,9.041) V47(-3.412,9.752) V48(-3.412,10.463) V50(-3.386,11.137) Y4(-2.439,-11.137) Y6(-2.439,-10.463) Y7(-2.439,-9.752) Y9(-2.439,-9.041) Y10(-2.439,-8.33) Y12(-2.439,-7.618) Y13(-2.439,-6.907) Y14(-2.439,-6.196) Y40(-2.439,6.196) Y41(-2.439,6.907) Y42(-2.439,7.618) Y44(-2.439,8.33) Y45(-2.439,9.041) Y47(-2.439,9.752) Y48(-2.439,10.463) Y50(-2.439,11.137)
